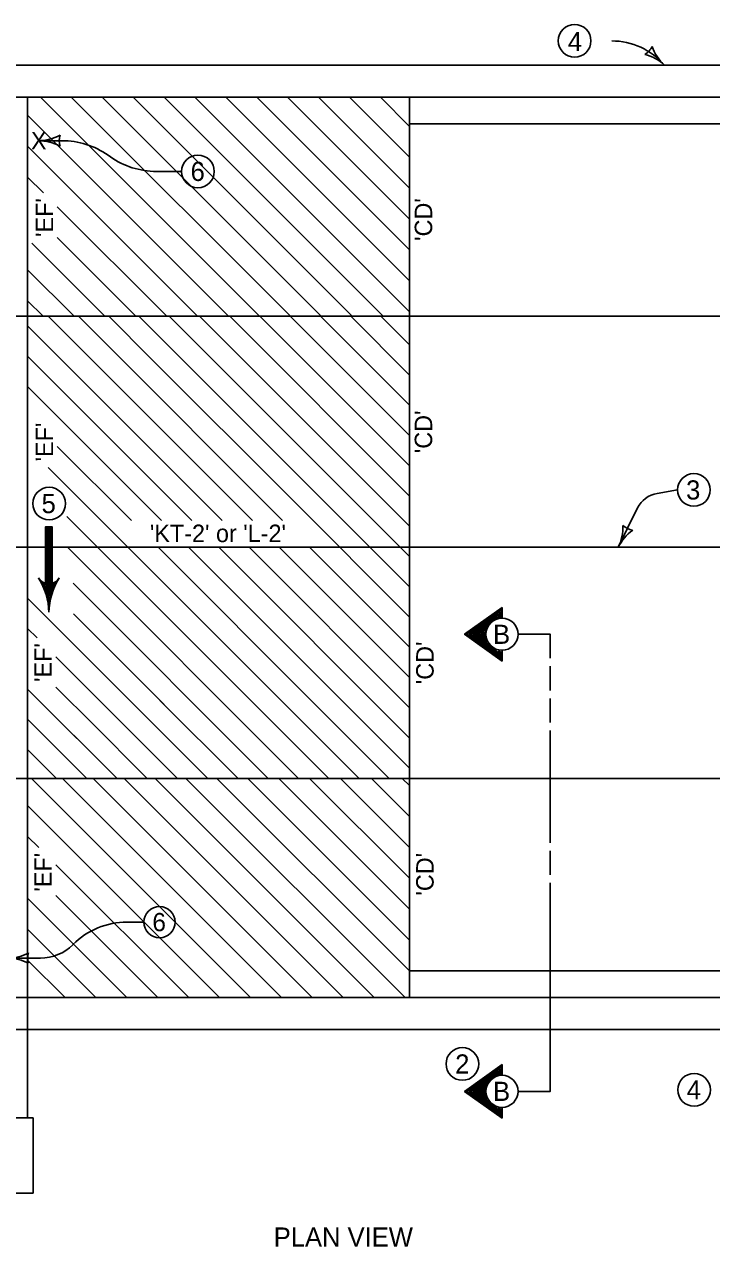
# Model space of a CAD drawing. Extents: x 10045 to 81668, y 6370 to 11018.
# Drawn here: x 18102 to 18762, y 6425 to 7599 of the extents above; entities that cross this region are included whole.
import ezdxf

# ---------------------------------------------------------------- set-up
doc = ezdxf.new("R2010")
doc.units = 0
for name, color, linetype in [('Alignment', 7, 'Continuous'), ('Default', 7, 'Continuous'), ('dsnStdLineWork', 7, 'Continuous')]:
    doc.layers.add(name, color=color, linetype=linetype)

msp = doc.modelspace()

# ---------------------------------------------------------------- linework, layer by layer
at = {"layer": 'Alignment'}
for p, q in [((18729.3, 7151.8), (18709.8, 7148.5)), ((18691, 7134.5), (18672.4, 7096.7)), ((18112.1, 6895.1), (18104.8, 6902.3)), ((19281.1, 6874.6), (17916.7, 6874.6)), ((18607, 6774.1), (18607, 6573.9)), ((18200.3, 6736.5), (18216.6, 6736.5)), ((18085.8, 6701.9), (18117.1, 6701.9))]:
    msp.add_line(p, q, dxfattribs=at)
for points in [[(18576.2, 7013.1), (18607, 7013.1), (18607, 6990)], [(18607, 6982.3), (18607, 6959.2)], [(18607, 6951.5), (18607, 6928.3)], [(18607, 6920.6), (18607, 6812.7)], [(18607, 6805), (18607, 6781.8)], [(18607, 6585.3), (18607, 6573.9), (18576.2, 6573.9)]]:
    msp.add_lwpolyline(points, dxfattribs=at)
for centre, radius, start, end in [((18666.1, 7516.5), 66.8, 40.5607, 90), ((18714.1, 7123.1), 25.7, 99.5323, 153.7542), ((18200.3, 6663.1), 73.4, 90, 135), ((18117.1, 6746), 44.1, 270, 315)]:
    msp.add_arc(centre, radius, start, end, dxfattribs=at)
at = {"layer": 'Default'}
msp.add_line((18841.9, 7529.2), (17916.7, 7529.2), dxfattribs=at)
at = {"layer": 'dsnStdLineWork'}
for p, q in [((18804.9, 7560), (17916.7, 7560)), ((18104.8, 7318.7), (18104.8, 7529.2)), ((18327.6, 7318.7), (18117.1, 7529.2)), ((18357.3, 7318.7), (18146.8, 7529.2)), ((18387, 7318.7), (18176.5, 7529.2)), ((18416.7, 7318.7), (18206.2, 7529.2)), ((18446.4, 7318.7), (18235.9, 7529.2)), ((18471.8, 7323), (18265.6, 7529.2)), ((18471.8, 7352.7), (18295.3, 7529.2)), ((18471.8, 7382.4), (18325, 7529.2)), ((18471.8, 7412.1), (18354.7, 7529.2)), ((18471.8, 7441.8), (18384.4, 7529.2)), ((18471.8, 7471.5), (18414.1, 7529.2)), ((18471.8, 7501.2), (18443.8, 7529.2)), ((18841.9, 7529.2), (18471.8, 7529.2)), ((18471.8, 7529.2), (18841.9, 7529.2)), ((18471.8, 7529.2), (18471.8, 6874.6)), ((18297.9, 7318.7), (18104.8, 7511.8)), ((18104.8, 7318.7), (18104.8, 7503.7)), ((18471.8, 7318.7), (18471.8, 7503.7)), ((18471.8, 7318.7), (18471.8, 7503.7)), ((18471.8, 7503.7), (18841.8, 7503.7)), ((18268.2, 7318.7), (18104.8, 7482.1)), ((18115.1, 7487.4), (18137.9, 7487.4)), ((18182.1, 7473.4), (18184.4, 7471.8)), ((18228.6, 7457.9), (18252.8, 7457.9)), ((18120, 7437.2), (18104.8, 7452.4)), ((18238.5, 7318.7), (18133.3, 7424)), ((18179.1, 7318.7), (18108.8, 7389)), ((18208.8, 7318.7), (18133.3, 7394.3)), ((18149.4, 7318.7), (18104.8, 7363.3)), ((18119.7, 7318.7), (18104.8, 7333.6)), ((17916.7, 7318.7), (19327.8, 7318.7)), ((18104.8, 6874.6), (18104.8, 7318.7)), ((18133.1, 7310.2), (18124.6, 7318.7)), ((18175.5, 7296.9), (18153.7, 7318.7)), ((18223.8, 7277.6), (18182.8, 7318.7)), ((18249.8, 7280.7), (18211.8, 7318.7)), ((18267.2, 7292.4), (18240.9, 7318.7)), ((18471.8, 7116.9), (18270, 7318.7)), ((18471.8, 7145.9), (18299.1, 7318.7)), ((18471.8, 7175), (18328.1, 7318.7)), ((18471.8, 7204.1), (18357.2, 7318.7)), ((18471.8, 7233.2), (18386.3, 7318.7)), ((18471.8, 7262.2), (18415.4, 7318.7)), ((18471.8, 7291.3), (18444.4, 7318.7)), ((18841.8, 7318.7), (18471.8, 7318.7)), ((18471.8, 7318.7), (18471.8, 6874.6)), ((18841.8, 7318.7), (18471.8, 7318.7)), ((18291.7, 7122.5), (18104.8, 7309.4)), ((18320.8, 7122.5), (18133.1, 7310.2)), ((18349.9, 7122.5), (18175.5, 7296.9)), ((18471.8, 7087.8), (18267.2, 7292.4)), ((18262.7, 7122.5), (18104.8, 7280.3)), ((18223.8, 7277.6), (18230.7, 7270.8)), ((18358.3, 7143.2), (18223.8, 7277.6)), ((18471.8, 7058.7), (18249.8, 7280.7)), ((18233.6, 7122.5), (18104.8, 7251.2)), ((18472.3, 7208.8), (18471.8, 7209.2)), ((18204.5, 7122.5), (18133.3, 7193.7)), ((18423.3, 6874.6), (18124.6, 7173.3)), ((18471.8, 7029.6), (18358.3, 7143.2)), ((18394.2, 6874.6), (18142.6, 7126.3)), ((18125.2, 7062), (18125.2, 7116.5)), ((18841.9, 7096.7), (17325.6, 7096.7)), ((18365.2, 6874.6), (18143.1, 7096.7)), ((18382.9, 6944), (18230.3, 7096.7)), ((18397.5, 6958.6), (18259.4, 7096.7)), ((18471.8, 6913.3), (18288.5, 7096.7)), ((18471.8, 6942.4), (18317.6, 7096.7)), ((18471.8, 6971.5), (18346.6, 7096.7)), ((18471.8, 7000.6), (18375.7, 7096.7)), ((18121.9, 7062.1), (18121.9, 7062.1)), ((18128.3, 7062.1), (18128.3, 7062.1)), ((18336.1, 6874.6), (18148.6, 7062.1)), ((18219.7, 6932.9), (18104.8, 7047.7)), ((18236.1, 6945.5), (18149, 7032.6)), ((18113.9, 7009.6), (18104.8, 7018.6)), ((18191.2, 6932.3), (18132, 6991.5)), ((18152.2, 6913.1), (18104.8, 6960.5)), ((18168.7, 6925.7), (18132, 6962.4)), ((18471.8, 6884.3), (18397.5, 6958.6)), ((18307, 6874.6), (18232, 6949.6)), ((18452.4, 6874.6), (18382.9, 6944)), ((18136.7, 6899.5), (18104.8, 6931.4)), ((18219.8, 6874.6), (18164.3, 6930.1)), ((18248.9, 6874.6), (18191.2, 6932.3)), ((18277.9, 6874.6), (18219.7, 6932.9)), ((18190.7, 6874.6), (18149.1, 6916.2)), ((18132.6, 6874.6), (18112.1, 6895.1)), ((18161.6, 6874.6), (18136.7, 6899.5)), ((18104.8, 6664.1), (18104.8, 6874.6)), ((18319, 6664.1), (18108.5, 6874.6)), ((18348.7, 6664.1), (18138.2, 6874.6)), ((18378.4, 6664.1), (18167.9, 6874.6)), ((18408.1, 6664.1), (18197.6, 6874.6)), ((18437.8, 6664.1), (18227.3, 6874.6)), ((18467.5, 6664.1), (18257, 6874.6)), ((18471.7, 6689.6), (18286.7, 6874.6)), ((18471.8, 6719.2), (18316.4, 6874.6)), ((18471.8, 6748.9), (18346.1, 6874.6)), ((18471.8, 6778.6), (18375.8, 6874.6)), ((18471.8, 6808.3), (18405.5, 6874.6)), ((18471.8, 6838), (18435.2, 6874.6)), ((18471.8, 6867.7), (18464.9, 6874.6)), ((18471.8, 6874.6), (18471.8, 6689.6)), ((18471.8, 6874.6), (18471.8, 6689.6)), ((18471.8, 6874.6), (18471.8, 6664.1)), ((18471.8, 6689.6), (18471.8, 6874.6)), ((18471.8, 6874.6), (18841.8, 6874.6)), ((18471.8, 6874.6), (18841.8, 6874.6)), ((18289.3, 6664.1), (18104.8, 6848.6)), ((18115.7, 6808.1), (18104.8, 6818.9)), ((18259.6, 6664.1), (18132, 6791.7)), ((18200.2, 6664.1), (18104.8, 6759.5)), ((18229.9, 6664.1), (18132, 6762)), ((18170.5, 6664.1), (18104.8, 6729.8)), ((18140.8, 6664.1), (18104.8, 6700.1)), ((18841.8, 6689.6), (18471.8, 6689.6)), ((18841.9, 6664.1), (17916.7, 6664.1)), ((18104.8, 6664.1), (18104.8, 6548.4)), ((18804.9, 6633.3), (17916.7, 6633.3)), ((18110, 6548.4), (18093.5, 6548.4)), ((18110, 6548.4), (18110, 6476)), ((18110, 6476), (18093.5, 6476))]:
    msp.add_line(p, q, dxfattribs=at)
for points in [[(18841.8, 7511.4), (18841.9, 7511.4), (18841.9, 7529.2), (18471.8, 7529.2), (18471.8, 7503.7), (18841.8, 7503.7)], [(18841.8, 6681.9), (18841.8, 6689.6), (18471.8, 6689.6), (18471.8, 6664.1), (18841.9, 6664.1), (18841.9, 6681.9)]]:
    msp.add_lwpolyline(points, close=True, dxfattribs=at)
for points in [[(18104.8, 7318.7), (18104.8, 7318.7)], [(18122.1, 7062.1), (18122.1, 7116.5), (18128.3, 7116.5), (18128.3, 7062.1), (18123, 7062.2), (18122.8, 7115.8), (18127.7, 7115.7), (18127.5, 7063.3), (18123.8, 7063.1), (18123.6, 7115), (18126.9, 7114.9), (18126.9, 7063.9), (18124.6, 7063.8), (18124.3, 7114.4), (18126.2, 7114.4), (18126.1, 7064.6)], [(18118.1, 7063.5), (18121.8, 7061.2), (18127.2, 7061), (18131.9, 7062.9), (18128.5, 7054.9), (18125.8, 7045.5), (18125.2, 7042.8), (18123.8, 7049.6), (18120.4, 7059.5), (18118.9, 7062.5), (18130.3, 7061.4), (18125.4, 7046.9), (18121.1, 7061), (18129, 7060.5), (18125.3, 7050.5), (18123.1, 7059.7), (18127.7, 7060.1), (18125.6, 7053.7), (18124.2, 7058.6), (18126.4, 7058.8), (18125.7, 7056.5)], [(18560.7, 7028.5), (18560.7, 7038.8), (18524.8, 7013.1), (18560.7, 6987.4), (18560.7, 6997.7)], [(18559.7, 6996.7), (18559.8, 6989.3), (18526.7, 7013.1), (18559.9, 7037.2), (18559.7, 7029.3), (18558.3, 7028.9), (18558.8, 7034.6), (18528.9, 7013.1), (18558.8, 6991.3), (18558.5, 6996.9), (18557.4, 6997.1), (18557.5, 6993.4), (18530.9, 7013.2), (18557.6, 7032), (18557, 7028.8), (18555.9, 7028.5), (18556, 7029.6), (18533.1, 7012.9), (18556.4, 6995.4), (18555.2, 6997.3), (18535.2, 7012.7), (18547.5, 7022.5), (18546.7, 7020.7), (18537.3, 7012.7), (18546.4, 7005.7), (18545.5, 7007.6), (18539.2, 7012.4), (18545.5, 7017.9), (18544.9, 7015.5), (18540.8, 7012.4), (18545, 7009.1), (18544.8, 7010.8), (18542.4, 7012.3), (18544.7, 7013.7), (18544.5, 7012.2), (18543.8, 7012.3)], [(18104.8, 6874.6), (18104.8, 6874.6)], [(18560.7, 6589.3), (18560.7, 6599.6), (18524.8, 6573.9), (18560.7, 6548.2), (18560.7, 6558.5)], [(18559.7, 6557.5), (18559.8, 6550), (18526.7, 6573.9), (18559.9, 6598), (18559.7, 6590.1), (18558.3, 6589.7), (18558.8, 6595.4), (18528.9, 6573.9), (18558.8, 6552.1), (18558.5, 6557.6), (18557.4, 6557.9), (18557.5, 6554.2), (18530.9, 6574), (18557.6, 6592.8), (18557, 6589.6), (18555.9, 6589.3), (18556, 6590.4), (18533.1, 6573.7), (18556.4, 6556.2), (18555.2, 6558.1), (18535.2, 6573.5), (18547.5, 6583.3), (18546.7, 6581.5), (18537.3, 6573.5), (18546.4, 6566.5), (18545.5, 6568.3), (18539.2, 6573.2), (18545.5, 6578.7), (18544.9, 6576.3), (18540.8, 6573.2), (18545, 6569.9), (18544.8, 6571.6), (18542.4, 6573.1), (18544.7, 6574.5), (18544.5, 6573), (18543.8, 6573.1)]]:
    msp.add_lwpolyline(points, dxfattribs=at)
for centre, radius in [((18630.5, 7583.4), 15.7), ((18268.5, 7457.9), 15.7), ((18745.1, 7151.8), 15.7), ((18125.5, 7138.7), 15.7), ((18560.7, 7013.1), 15.4), ((18231.6, 6736.5), 15), ((18522.6, 6600.2), 15.7), ((18560.7, 6573.9), 15.4), ((18745.3, 6575.3), 15.7)]:
    msp.add_circle(centre, radius, dxfattribs=at)
for centre, radius, start, end in [((18689.5, 7585.2), 17.1, 299.4947, 334.9614), ((18746.9, 7592.6), 44.4, 199.1556, 227.2281), ((18686.7, 7527.4), 44.4, 47.2281, 75.3006), ((18115.1, 7531.8), 44.4, 270, 298.0725), ((18115.1, 7531.8), 44.4, 270, 298.0725), ((18152.3, 7487.4), 17.1, 162.2666, 197.7334), ((18152.3, 7487.4), 17.1, 162.2666, 197.7334), ((18115.1, 7443), 44.4, 61.9275, 90), ((18115.1, 7443), 44.4, 61.9275, 90), ((18137.9, 7410.3), 77.1, 55.0007, 90), ((18228.6, 7535), 77.1, 235.0001, 270), ((18632.6, 7116.3), 44.4, 333.7545, 1.8269), ((18688.8, 7130), 17.1, 226.0211, 261.4878), ((18712.2, 7077), 44.4, 125.682, 153.7545), ((18125.2, 7073.3), 11.6, 211.7147, 328.2853), ((18059, 7032.3), 66.3, 1.6842, 31.7143), ((18191.5, 7032.3), 66.3, 148.2857, 178.3158), ((18085.8, 6744.2), 42.3, 270, 298.0725), ((18121.2, 6701.9), 16.3, 162.2666, 197.7334), ((18085.8, 6659.6), 42.3, 61.9275, 90)]:
    msp.add_arc(centre, radius, start, end, dxfattribs=at)

# ---------------------------------------------------------------- texts
at = {"layer": 'Alignment'}
for s, height, p in [('4', 18.4, (18624, 7573.5)), ('X', 16.8, (18108, 7479)), ('6', 18.4, (18261.4, 7448.7)), ('3', 18.4, (18737.6, 7142.6)), ('5', 18.4, (18118.2, 7129.5)), ("'KT-2' or 'L-2'", 16.8, (18222.3, 7101.7)), ('B', 18.4, (18552.1, 7003.9)), ('6', 17.5, (18224.7, 6727.8)), ('2', 18.4, (18515.7, 6591)), ('B', 18.4, (18552.1, 6564.7)), ('4', 18.4, (18738.2, 6566.1)), ('PLAN VIEW', 18.37, (18341.3, 6424.7))]:
    msp.add_text(s, height=height, dxfattribs=at).set_placement(p)
for s, p in [("'EF'", (18129.3, 7394.9)), ("'CD'", (18493.6, 7391.1)), ("'CD'", (18493.6, 7187.1)), ("'EF'", (18129.3, 7179.2)), ("'EF'", (18128, 6967.3)), ("'CD'", (18495, 6965.1)), ("'EF'", (18128, 6765.8)), ("'CD'", (18495, 6762))]:
    msp.add_text(s, height=16.8, rotation=90, dxfattribs=at).set_placement(p)

doc.saveas('drawing.dxf')
